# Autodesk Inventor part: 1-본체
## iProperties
Created: 2015-01
Part Number: 1-본체
Document SubType Name: Modeling
Designer: Administrator
Density: 2.71 g/cm^3
Material: 알루미늄-6061
Mass: 1021.15 g
Surface Area: 1059.8 cm^2
Volume: 376.807 cm^3
Author: Administrator
